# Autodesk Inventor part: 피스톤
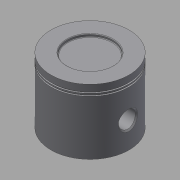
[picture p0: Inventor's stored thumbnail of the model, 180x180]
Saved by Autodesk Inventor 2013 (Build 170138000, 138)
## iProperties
Created: 2016-11
Part Number: 피스톤
Material: 강철, 탄소
Document SubType Name: Modeling
Designer: mduedu
Density: 7.87 g/cm^3
Mass: 273.351 g
Surface Area: 265.014 cm^2
Volume: 34.7333 cm^3
Author: mduedu
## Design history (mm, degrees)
sketch "스케치1"
  geometry: C1 r 30 at (0, 0); 1 further point
  constraints: 1 centre point, 1 coincident
  dimensions: "d0" = 60 diameter of C1
extrude "돌출1" new body sketch "스케치1" distance "d1" = 50; taper "d2" = 0 deg
sketch "스케치2"
  geometry: C1 r 28 at (0, 0); 1 further point
  constraints: 1 centre point, 1 coincident
  dimensions: "d3" = 56 diameter of C1
extrude "돌출2" cut sketch "스케치2" distance "d4" = 45; taper "d5" = 0 deg
sketch "스케치3"
  geometry: L1 (30, 0)-(30, 50) reference; L2 (30, 45)-(29, 45); L3 (29, 45)-(29, 44); L4 (29, 44)-(30, 44); L5 (30, 44)-(30, 45); L6 (30, 43)-(29, 43); L7 (29, 43)-(29, 42); L8 (29, 42)-(30, 42); L9 (30, 42)-(30, 43); L10 (30, 50)-(-30, 50) reference; L11 (0, 50)-(0, 0)
  constraints: 18 end point, 4 parallel, 3 equal length, 3 perpendicular, 2 horizontal, 2 point on line, 1 midpoint
  dimensions: "d6" = 1 distance of L2.start L2.end; "d8" = 5 distance between parallel lines of L10 L2; "d9" = 1 distance between parallel lines of L6 L4
revolve "회전1" sketch "스케치3" stored, may be unused: angle "d10" = 90 deg
node "작업 평면1"
sketch "스케치4"
  geometry: C1 r 10 at (20, 0); C2 r 6.5 at (20, 0); 1 further point
  constraints: 2 centre point, 1 coincident, 1 horizontal alignment
  dimensions: "d12" = 20 diameter of C1; "d13" = 13 diameter of C2; "d14" = 20 distance of point (0, 0) C1.centre
extrude "돌출3" join sketch "스케치4" stored distance "d15" = 11.75; taper "d16" = 0 deg
extrude "돌출4" cut sketch "스케치4" stored distance "d17" = 72; taper "d18" = 0 deg
fillet "모깎기1" dims "d19" = 3
fillet "모깎기2" dims "d20" = 3
chamfer "모따기1" distance "d21" = 1; stored, may be unused: second distance "d22" = 2, angle "d23" = 45 deg
chamfer "모따기2" distance "d24" = 1; stored, may be unused: second distance "d25" = 2, angle "d26" = 45 deg
sketch "스케치5"
  geometry: C1 r 17.5 at (0, 0); 1 further point
  constraints: 1 centre point, 1 coincident
  dimensions: "d27" = 35 diameter of C1
extrude "돌출5" cut sketch "스케치5" distance "d28" = 2; taper "d29" = 0 deg
fillet "모깎기3" dims "d30" = 0.5
node "솔리드1"
mirror "대칭1"
